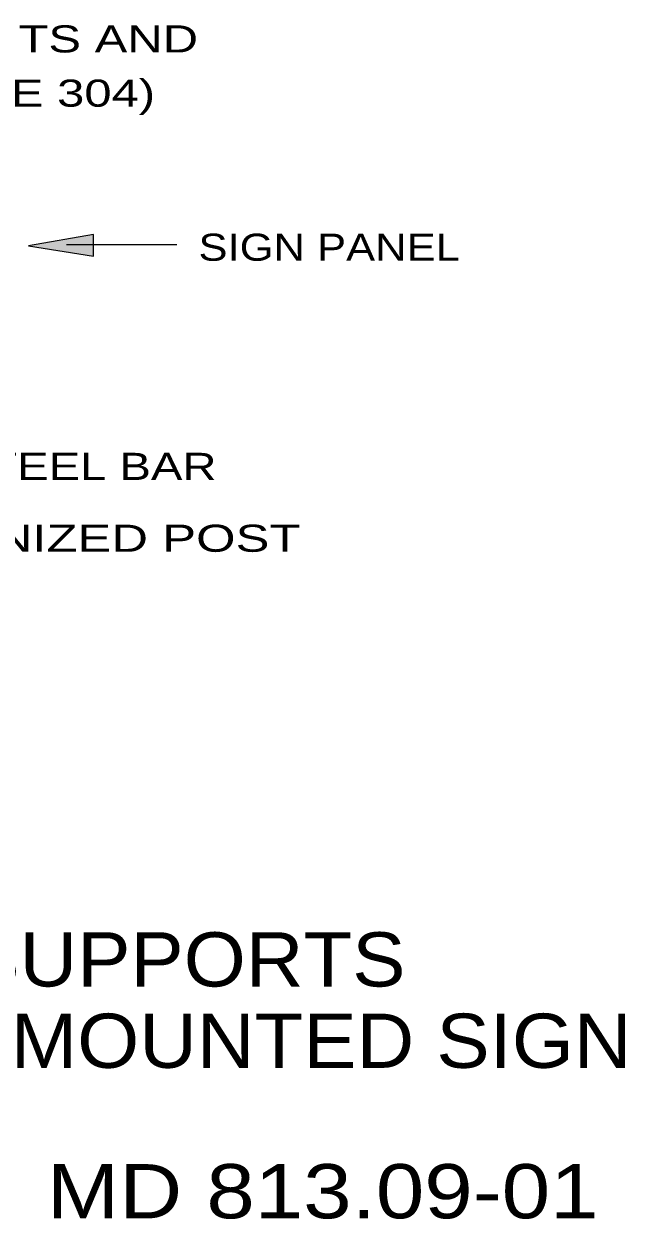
# Model space of a CAD drawing. Extents: x 5332.5 to 5339, y 1824.9 to 1835.1.
# Drawn here: x 5337.54 to 5338.869, y 1824.937 to 1827.582 of the extents above; entities that cross this region are included whole.
import ezdxf
from ezdxf.enums import TextEntityAlignment as Align

# ---------------------------------------------------------------- set-up
doc = ezdxf.new("R2010")
doc.units = 0
doc.header["$LTSCALE"] = 0.024
doc.layers.add('10', color=7, linetype='Continuous', lineweight=13)
doc.layers.add('12', color=7, linetype='Continuous', lineweight=53)
doc.layers.add('13', color=7, linetype='Continuous')

msp = doc.modelspace()

# ---------------------------------------------------------------- hatches: boundary and pattern name
at = {"layer": '10'}
msp.add_hatch(color=256, dxfattribs=at).paths.add_polyline_path([(5337.694, 1827.068), (5337.694, 1827.116), (5337.55, 1827.091)])
msp.add_hatch(color=256, dxfattribs=at).paths.add_polyline_path([(5337.694, 1827.068), (5337.694, 1827.116), (5337.55, 1827.091)])
msp.add_hatch(color=256, dxfattribs=at).paths.add_polyline_path([(5337.694, 1827.068), (5337.694, 1827.116), (5337.55, 1827.091)])
msp.add_hatch(color=256, dxfattribs=at).paths.add_polyline_path([(5337.694, 1827.068), (5337.694, 1827.116), (5337.55, 1827.091)])
msp.add_hatch(color=256, dxfattribs=at).paths.add_polyline_path([(5337.694, 1827.068), (5337.694, 1827.116), (5337.55, 1827.091)])
msp.add_hatch(color=256, dxfattribs=at).paths.add_polyline_path([(5337.694, 1827.068), (5337.694, 1827.116), (5337.55, 1827.091)])
msp.add_hatch(color=256, dxfattribs=at).paths.add_polyline_path([(5337.694, 1827.068), (5337.694, 1827.116), (5337.55, 1827.091)])
msp.add_hatch(color=256, dxfattribs=at).paths.add_polyline_path([(5337.694, 1827.068), (5337.694, 1827.116), (5337.55, 1827.091)])
msp.add_hatch(color=256, dxfattribs=at).paths.add_polyline_path([(5337.694, 1827.068), (5337.694, 1827.116), (5337.55, 1827.091)])
msp.add_hatch(color=256, dxfattribs=at).paths.add_polyline_path([(5337.694, 1827.068), (5337.694, 1827.116), (5337.55, 1827.091)])
msp.add_hatch(color=256, dxfattribs=at).paths.add_polyline_path([(5337.694, 1827.068), (5337.694, 1827.116), (5337.55, 1827.091)])

# ---------------------------------------------------------------- linework, layer by layer
msp.add_line((5337.634, 1827.094), (5337.878, 1827.094), dxfattribs=at)
msp.add_line((5337.634, 1827.094), (5337.878, 1827.094), dxfattribs=at)
msp.add_line((5337.634, 1827.094), (5337.878, 1827.094), dxfattribs=at)
msp.add_line((5337.634, 1827.094), (5337.878, 1827.094), dxfattribs=at)
msp.add_line((5337.634, 1827.094), (5337.878, 1827.094), dxfattribs=at)
msp.add_line((5337.634, 1827.094), (5337.878, 1827.094), dxfattribs=at)
msp.add_line((5337.634, 1827.094), (5337.878, 1827.094), dxfattribs=at)
msp.add_line((5337.634, 1827.094), (5337.878, 1827.094), dxfattribs=at)
msp.add_line((5337.634, 1827.094), (5337.878, 1827.094), dxfattribs=at)
msp.add_line((5337.634, 1827.094), (5337.878, 1827.094), dxfattribs=at)
msp.add_line((5337.634, 1827.094), (5337.878, 1827.094), dxfattribs=at)
msp.add_lwpolyline([(5337.694, 1827.068), (5337.694, 1827.116), (5337.55, 1827.091)], close=True, dxfattribs=at)
msp.add_lwpolyline([(5337.694, 1827.068), (5337.694, 1827.116), (5337.55, 1827.091)], close=True, dxfattribs=at)
msp.add_lwpolyline([(5337.694, 1827.068), (5337.694, 1827.116), (5337.55, 1827.091)], close=True, dxfattribs=at)
msp.add_lwpolyline([(5337.694, 1827.068), (5337.694, 1827.116), (5337.55, 1827.091)], close=True, dxfattribs=at)
msp.add_lwpolyline([(5337.694, 1827.068), (5337.694, 1827.116), (5337.55, 1827.091)], close=True, dxfattribs=at)
msp.add_lwpolyline([(5337.694, 1827.068), (5337.694, 1827.116), (5337.55, 1827.091)], close=True, dxfattribs=at)
msp.add_lwpolyline([(5337.694, 1827.068), (5337.694, 1827.116), (5337.55, 1827.091)], close=True, dxfattribs=at)
msp.add_lwpolyline([(5337.694, 1827.068), (5337.694, 1827.116), (5337.55, 1827.091)], close=True, dxfattribs=at)
msp.add_lwpolyline([(5337.694, 1827.068), (5337.694, 1827.116), (5337.55, 1827.091)], close=True, dxfattribs=at)
msp.add_lwpolyline([(5337.694, 1827.068), (5337.694, 1827.116), (5337.55, 1827.091)], close=True, dxfattribs=at)
msp.add_lwpolyline([(5337.694, 1827.068), (5337.694, 1827.116), (5337.55, 1827.091)], close=True, dxfattribs=at)

# ---------------------------------------------------------------- texts
at = {"layer": '12'}
for s, width, p in [('1/4" x 1" BOLTS, NUTS AND', 1.35, (5336.524, 1827.519)), ('WASHER (S.S. TYPE 304)', 1.35, (5336.524, 1827.399)), ('SIGN PANEL', 1.2, (5337.926, 1827.058)), ('3" x 1/4" GALVANIZED STEEL BAR', 1.3, (5336.286, 1826.573)), ('TS 6" x 4" x 3/8" GALVANIZED POST', 1.4, (5336.259, 1826.414))]:
    msp.add_text(s, height=0.06, dxfattribs=dict(at, width=width)).set_placement(p)
at = {"layer": '13'}
for s, width, p in [('SPECIAL SIGN SUPPORTS', 1.1, (5337.2605, 1825.452)), ('CONCRETE BARRIER MOUNTED SIGN', 1.1, (5337.2605, 1825.272)), ('MD 813.09-01', 1.2, (5338.2005, 1824.939))]:
    msp.add_text(s, height=0.12, dxfattribs=dict(at, width=width)).set_placement(p, align=Align.CENTER)

doc.saveas('drawing.dxf')
